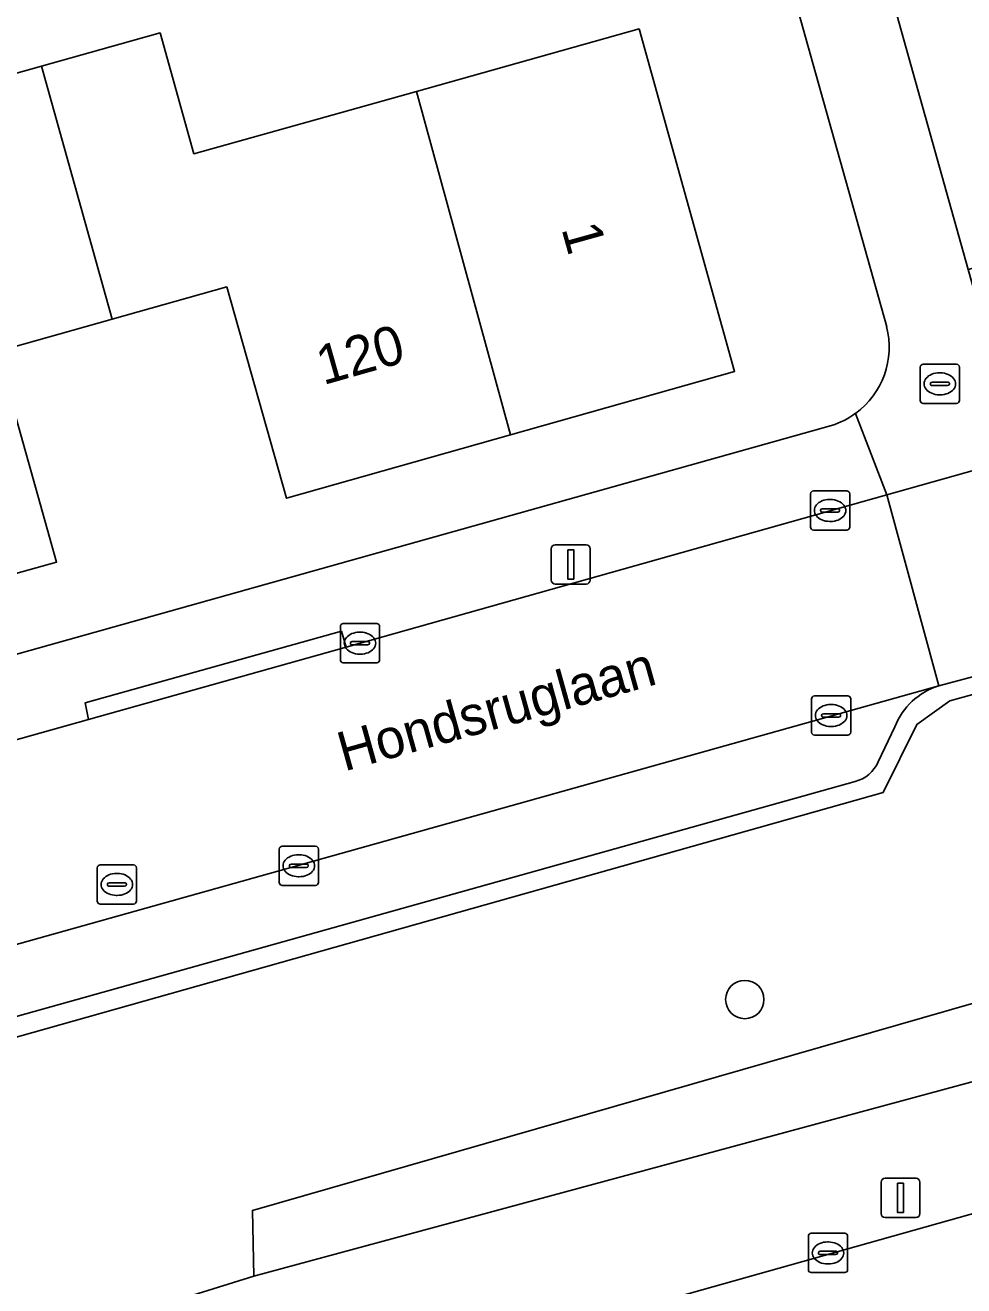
# Model space of a CAD drawing. Extents: x 159626 to 160723, y 388173 to 389416.
# Drawn here: x 160071.4 to 160095.34, y 388295.24 to 388327.38 of the extents above; entities that cross this region are included whole.
import ezdxf

# ---------------------------------------------------------------- set-up
doc = ezdxf.new("R2010")
doc.units = 0
for name, color, linetype in [('IMGEO_Boom', 7, 'Continuous'), ('IMGEO_Brandkraan', 7, 'Continuous'), ('IMGEO_Erf', 7, 'Continuous'), ('IMGEO_Groenvoorziening', 7, 'Continuous'), ('IMGEO_Kolk', 7, 'Continuous'), ('IMGEO_Lichtmast', 7, 'Continuous'), ('IMGEO_Muur', 7, 'Continuous'), ('IMGEO_Openbare_ruimte_label', 7, 'Continuous'), ('IMGEO_Pand', 7, 'Continuous'), ('IMGEO_Pand_nummerreeks', 7, 'Continuous'), ('IMGEO_Parkeervlak_open', 7, 'Continuous'), ('IMGEO_Rijbaan_lokaal_open', 7, 'Continuous'), ('IMGEO_Rijbaan_regionaal_gesloten', 7, 'Continuous'), ('IMGEO_Rioolput', 7, 'Continuous'), ('IMGEO_Voetpad_open', 7, 'Continuous')]:
    doc.layers.add(name, color=color, linetype=linetype)

msp = doc.modelspace()

# ---------------------------------------------------------------- linework, layer by layer
at = {"layer": 'IMGEO_Boom'}
msp.add_circle((160089.755, 388302.536), 0.489, dxfattribs=at)
at = {"layer": 'IMGEO_Brandkraan'}
for p, q in [((160094.304, 388318.738), (160095.156, 388318.738)), ((160094.229, 388317.812), (160094.229, 388318.664)), ((160094.717, 388318.518), (160094.742, 388318.518)), ((160095.23, 388318.664), (160095.23, 388317.812)), ((160094.488, 388318.232), (160094.488, 388318.244)), ((160094.926, 388318.195), (160094.528, 388318.195)), ((160094.531, 388318.281), (160094.929, 388318.281)), ((160094.972, 388318.244), (160094.972, 388318.232)), ((160094.74, 388317.958), (160094.715, 388317.958)), ((160095.156, 388317.738), (160094.304, 388317.738))]:
    msp.add_line(p, q, dxfattribs=at)
for points in [[(160094.304, 388318.738), (160095.156, 388318.738)], [(160094.229, 388317.812), (160094.229, 388318.664)], [(160095.23, 388318.664), (160095.23, 388317.812)], [(160095.156, 388317.738), (160094.304, 388317.738)]]:
    msp.add_lwpolyline(points, dxfattribs=at)
for centre, radius, start, end in [((160094.306, 388318.662), 0.0765, 91.552, 178.448), ((160094.306, 388318.662), 0.0765, 91.552, 178.448), ((160095.154, 388318.662), 0.0765, 1.552, 88.448), ((160095.154, 388318.662), 0.0765, 1.552, 88.448), ((160094.528, 388318.241), 0.0403, 85.8775, 175.7526), ((160094.525, 388318.231), 0.0366, 178.938, 274.7102), ((160094.929, 388318.238), 0.043, 264.8664, 352.4533), ((160094.933, 388318.243), 0.0386, 1.7309, 96.639), ((160094.306, 388317.814), 0.0765, 181.552, 268.448), ((160094.306, 388317.814), 0.0765, 181.552, 268.448), ((160095.154, 388317.814), 0.0765, 271.552, 358.448), ((160095.154, 388317.814), 0.0765, 271.552, 358.448)]:
    msp.add_arc(centre, radius, start, end, dxfattribs=at)
for centre, major_axis, ratio, start_param, end_param in [((160094.716, 388318.238), (-0.387, 0.002), 0.722429, 4.712389, 7.853982), ((160094.741, 388318.238), (-0.39, 0.002), 0.717154, 1.570796, 4.712389)]:
    msp.add_ellipse(centre, major_axis=major_axis, ratio=ratio, start_param=start_param, end_param=end_param, dxfattribs=at)
at = {"layer": 'IMGEO_Erf'}
for points in [[(160093.373, 388319.695), (160091.694, 388325.686), (160087.996, 388338.877), (160074.295, 388387.755)], [(160070.029, 388325.837), (160071.818, 388326.338), (160074.843, 388327.186), (160075.705, 388324.106), (160081.382, 388325.697), (160087.061, 388327.289), (160089.494, 388318.556), (160083.782, 388316.937), (160078.07, 388315.318), (160076.543, 388320.71), (160073.618, 388319.888), (160070.691, 388319.065), (160072.202, 388313.692), (160066.465, 388312.092)], [(160039.23, 388302.377), (160091.966, 388317.174)]]:
    msp.add_lwpolyline(points, dxfattribs=at)
for centre, radius, start, end in [((160091.34, 388319.177), 2.098, 306.2576, 14.31), ((160091.336, 388319.183), 2.105, 287.4032, 306.2475)]:
    msp.add_arc(centre, radius, start, end, dxfattribs=at)
at = {"layer": 'IMGEO_Groenvoorziening'}
for points in [[(160111.162, 388314.606), (160094.986, 388310.154), (160094.139, 388309.551), (160093.281, 388307.812), (160046.081, 388294.496), (160053.63, 388288.927), (160054.524, 388285.955)], [(160114.554, 388302.646), (160113.805, 388305.375), (160077.234, 388295.478), (160060.904, 388290.398), (160060.65, 388290.319), (160055.595, 388289.524), (160056.59, 388286.1), (160101.232, 388298.671)], [(160055.017, 388285.657), (160056.59, 388286.1), (160055.595, 388289.524), (160060.65, 388290.319), (160060.904, 388290.398), (160077.234, 388295.478), (160077.196, 388297.158), (160101.531, 388304.151)]]:
    msp.add_lwpolyline(points, dxfattribs=at)
msp.add_lwpolyline([(160077.234, 388295.478), (160113.805, 388305.375), (160101.531, 388304.151), (160077.196, 388297.158)], close=True, dxfattribs=at)
at = {"layer": 'IMGEO_Kolk'}
for p, q in [((160091.429, 388314.582), (160091.429, 388315.434)), ((160091.504, 388315.508), (160092.356, 388315.508)), ((160091.917, 388315.288), (160091.942, 388315.288)), ((160092.43, 388315.434), (160092.43, 388314.582)), ((160091.688, 388315.002), (160091.688, 388315.014)), ((160092.126, 388314.965), (160091.728, 388314.965)), ((160091.731, 388315.051), (160092.129, 388315.051)), ((160092.172, 388315.014), (160092.172, 388315.002)), ((160091.94, 388314.728), (160091.915, 388314.728)), ((160092.356, 388314.508), (160091.504, 388314.508)), ((160079.441, 388311.198), (160079.441, 388312.05)), ((160079.516, 388312.124), (160080.368, 388312.124)), ((160080.442, 388312.05), (160080.442, 388311.198)), ((160079.743, 388311.667), (160080.141, 388311.667)), ((160079.929, 388311.904), (160079.954, 388311.904)), ((160079.7, 388311.618), (160079.7, 388311.63)), ((160080.138, 388311.581), (160079.74, 388311.581)), ((160079.952, 388311.344), (160079.927, 388311.344)), ((160080.184, 388311.63), (160080.184, 388311.618)), ((160080.368, 388311.124), (160079.516, 388311.124)), ((160091.456, 388309.353), (160091.456, 388310.205)), ((160091.531, 388310.279), (160092.383, 388310.279)), ((160091.944, 388310.059), (160091.969, 388310.059)), ((160092.457, 388310.205), (160092.457, 388309.353)), ((160091.715, 388309.773), (160091.715, 388309.785)), ((160092.153, 388309.736), (160091.755, 388309.736)), ((160091.758, 388309.822), (160092.156, 388309.822)), ((160092.199, 388309.785), (160092.199, 388309.773)), ((160091.967, 388309.499), (160091.942, 388309.499)), ((160092.383, 388309.279), (160091.531, 388309.279)), ((160077.881, 388305.521), (160077.881, 388306.373)), ((160077.956, 388306.447), (160078.808, 388306.447)), ((160078.369, 388306.227), (160078.394, 388306.227)), ((160078.882, 388306.373), (160078.882, 388305.521)), ((160078.14, 388305.941), (160078.14, 388305.953)), ((160078.578, 388305.904), (160078.18, 388305.904)), ((160078.183, 388305.99), (160078.581, 388305.99)), ((160078.624, 388305.953), (160078.624, 388305.941)), ((160078.392, 388305.667), (160078.367, 388305.667)), ((160078.808, 388305.447), (160077.956, 388305.447)), ((160091.451, 388296.573), (160092.303, 388296.573)), ((160091.376, 388295.647), (160091.376, 388296.499)), ((160091.864, 388296.353), (160091.889, 388296.353)), ((160092.377, 388296.499), (160092.377, 388295.647)), ((160091.635, 388296.067), (160091.635, 388296.079)), ((160092.073, 388296.03), (160091.675, 388296.03)), ((160091.678, 388296.116), (160092.076, 388296.116)), ((160092.119, 388296.079), (160092.119, 388296.067)), ((160091.887, 388295.793), (160091.862, 388295.793)), ((160092.303, 388295.573), (160091.451, 388295.573))]:
    msp.add_line(p, q, dxfattribs=at)
for points in [[(160091.429, 388314.582), (160091.429, 388315.434)], [(160091.504, 388315.508), (160092.356, 388315.508)], [(160092.43, 388315.434), (160092.43, 388314.582)], [(160092.356, 388314.508), (160091.504, 388314.508)], [(160079.441, 388311.198), (160079.441, 388312.05)], [(160079.516, 388312.124), (160080.368, 388312.124)], [(160080.442, 388312.05), (160080.442, 388311.198)], [(160080.368, 388311.124), (160079.516, 388311.124)], [(160091.456, 388309.353), (160091.456, 388310.205)], [(160091.531, 388310.279), (160092.383, 388310.279)], [(160092.457, 388310.205), (160092.457, 388309.353)], [(160092.383, 388309.279), (160091.531, 388309.279)], [(160077.881, 388305.521), (160077.881, 388306.373)], [(160077.956, 388306.447), (160078.808, 388306.447)], [(160078.882, 388306.373), (160078.882, 388305.521)], [(160078.808, 388305.447), (160077.956, 388305.447)], [(160091.451, 388296.573), (160092.303, 388296.573)], [(160091.376, 388295.647), (160091.376, 388296.499)], [(160092.377, 388296.499), (160092.377, 388295.647)], [(160092.303, 388295.573), (160091.451, 388295.573)]]:
    msp.add_lwpolyline(points, dxfattribs=at)
for centre, radius, start, end in [((160091.506, 388315.432), 0.0765, 91.552, 178.448), ((160091.506, 388315.432), 0.0765, 91.552, 178.448), ((160092.354, 388315.432), 0.0765, 1.552, 88.448), ((160092.354, 388315.432), 0.0765, 1.552, 88.448), ((160091.728, 388315.011), 0.0403, 85.8775, 175.7526), ((160091.725, 388315.001), 0.0366, 178.938, 274.7102), ((160092.129, 388315.008), 0.043, 264.8664, 352.4533), ((160092.133, 388315.013), 0.0386, 1.7309, 96.639), ((160091.506, 388314.584), 0.0765, 181.552, 268.448), ((160091.506, 388314.584), 0.0765, 181.552, 268.448), ((160092.354, 388314.584), 0.0765, 271.552, 358.448), ((160092.354, 388314.584), 0.0765, 271.552, 358.448), ((160079.518, 388312.048), 0.0765, 91.552, 178.448), ((160079.518, 388312.048), 0.0765, 91.552, 178.448), ((160080.366, 388312.048), 0.0765, 1.552, 88.448), ((160080.366, 388312.048), 0.0765, 1.552, 88.448), ((160079.74, 388311.627), 0.0403, 85.8775, 175.7526), ((160080.145, 388311.629), 0.0386, 1.7309, 96.639), ((160079.737, 388311.617), 0.0366, 178.938, 274.7102), ((160080.141, 388311.624), 0.043, 264.8664, 352.4533), ((160079.518, 388311.2), 0.0765, 181.552, 268.448), ((160079.518, 388311.2), 0.0765, 181.552, 268.448), ((160080.366, 388311.2), 0.0765, 271.552, 358.448), ((160080.366, 388311.2), 0.0765, 271.552, 358.448), ((160091.533, 388310.203), 0.0765, 91.552, 178.448), ((160091.533, 388310.203), 0.0765, 91.552, 178.448), ((160092.381, 388310.203), 0.0765, 1.552, 88.448), ((160092.381, 388310.203), 0.0765, 1.552, 88.448), ((160091.755, 388309.782), 0.0403, 85.8775, 175.7526), ((160091.752, 388309.772), 0.0366, 178.938, 274.7102), ((160092.156, 388309.779), 0.043, 264.8664, 352.4533), ((160092.16, 388309.784), 0.0386, 1.7309, 96.639), ((160091.533, 388309.355), 0.0765, 181.552, 268.448), ((160091.533, 388309.355), 0.0765, 181.552, 268.448), ((160092.381, 388309.355), 0.0765, 271.552, 358.448), ((160092.381, 388309.355), 0.0765, 271.552, 358.448), ((160077.958, 388306.371), 0.0765, 91.552, 178.448), ((160077.958, 388306.371), 0.0765, 91.552, 178.448), ((160078.806, 388306.371), 0.0765, 1.552, 88.448), ((160078.806, 388306.371), 0.0765, 1.552, 88.448), ((160078.18, 388305.95), 0.0403, 85.8775, 175.7526), ((160078.177, 388305.94), 0.0366, 178.938, 274.7102), ((160078.581, 388305.947), 0.043, 264.8664, 352.4533), ((160078.585, 388305.952), 0.0386, 1.7309, 96.639), ((160077.958, 388305.523), 0.0765, 181.552, 268.448), ((160077.958, 388305.523), 0.0765, 181.552, 268.448), ((160078.806, 388305.523), 0.0765, 271.552, 358.448), ((160078.806, 388305.523), 0.0765, 271.552, 358.448), ((160091.453, 388296.497), 0.0765, 91.552, 178.448), ((160091.453, 388296.497), 0.0765, 91.552, 178.448), ((160092.301, 388296.497), 0.0765, 1.552, 88.448), ((160092.301, 388296.497), 0.0765, 1.552, 88.448), ((160091.675, 388296.076), 0.0403, 85.8775, 175.7526), ((160091.672, 388296.066), 0.0366, 178.938, 274.7102), ((160092.076, 388296.073), 0.043, 264.8664, 352.4533), ((160092.08, 388296.078), 0.0386, 1.7309, 96.639), ((160091.453, 388295.649), 0.0765, 181.552, 268.448), ((160091.453, 388295.649), 0.0765, 181.552, 268.448), ((160092.301, 388295.649), 0.0765, 271.552, 358.448), ((160092.301, 388295.649), 0.0765, 271.552, 358.448)]:
    msp.add_arc(centre, radius, start, end, dxfattribs=at)
for centre, major_axis, ratio, start_param, end_param in [((160091.916, 388315.008), (-0.387, 0.002), 0.722429, 4.712389, 7.853982), ((160091.941, 388315.008), (-0.39, 0.002), 0.717154, 1.570796, 4.712389), ((160079.928, 388311.624), (-0.387, 0.002), 0.722429, 4.712389, 7.853982), ((160079.953, 388311.624), (-0.39, 0.002), 0.717154, 1.570796, 4.712389), ((160091.943, 388309.779), (-0.387, 0.002), 0.722429, 4.712389, 7.853982), ((160091.968, 388309.779), (-0.39, 0.002), 0.717154, 1.570796, 4.712389), ((160078.368, 388305.947), (-0.387, 0.002), 0.722429, 4.712389, 7.853982), ((160078.393, 388305.947), (-0.39, 0.002), 0.717154, 1.570796, 4.712389), ((160091.863, 388296.073), (-0.387, 0.002), 0.722429, 4.712389, 7.853982), ((160091.888, 388296.073), (-0.39, 0.002), 0.717154, 1.570796, 4.712389)]:
    msp.add_ellipse(centre, major_axis=major_axis, ratio=ratio, start_param=start_param, end_param=end_param, dxfattribs=at)
at = {"layer": 'IMGEO_Lichtmast'}
for p, q in [((160084.821, 388313.232), (160084.821, 388314.032)), ((160084.821, 388314.032), (160084.821, 388313.232)), ((160084.921, 388314.132), (160085.711, 388314.132)), ((160085.711, 388314.132), (160084.921, 388314.132)), ((160085.811, 388314.032), (160085.811, 388313.232)), ((160085.811, 388313.232), (160085.811, 388314.032)), ((160085.711, 388313.132), (160084.921, 388313.132)), ((160084.921, 388313.132), (160085.711, 388313.132)), ((160093.232, 388297.077), (160093.232, 388297.877)), ((160093.232, 388297.877), (160093.232, 388297.077)), ((160093.332, 388297.977), (160094.122, 388297.977)), ((160094.122, 388297.977), (160093.332, 388297.977)), ((160094.222, 388297.877), (160094.222, 388297.077)), ((160094.222, 388297.077), (160094.222, 388297.877)), ((160094.122, 388296.977), (160093.332, 388296.977)), ((160093.332, 388296.977), (160094.122, 388296.977))]:
    msp.add_line(p, q, dxfattribs=at)
for points in [[(160085.241, 388314.007), (160085.391, 388314.007), (160085.391, 388313.257), (160085.241, 388313.257), (160085.241, 388314.007)], [(160093.652, 388297.852), (160093.802, 388297.852), (160093.802, 388297.102), (160093.652, 388297.102), (160093.652, 388297.852)]]:
    msp.add_lwpolyline(points, dxfattribs=at)
for centre, start, end in [((160084.921, 388314.032), 90, 180), ((160084.921, 388314.032), 90, 180), ((160085.711, 388314.032), 0, 90), ((160085.711, 388314.032), 360, 90), ((160084.921, 388313.232), 180, 270), ((160084.921, 388313.232), 180, 270), ((160085.711, 388313.232), 270, 0), ((160085.711, 388313.232), 270, 0), ((160093.332, 388297.877), 90, 180), ((160093.332, 388297.877), 90, 180), ((160094.122, 388297.877), 0, 90), ((160094.122, 388297.877), 360, 90), ((160093.332, 388297.077), 180, 270), ((160093.332, 388297.077), 180, 270), ((160094.122, 388297.077), 270, 0), ((160094.122, 388297.077), 270, 0)]:
    msp.add_arc(centre, 0.1, start, end, dxfattribs=at)
at = {"layer": 'IMGEO_Muur'}
msp.add_lwpolyline([(160091.694, 388325.686), (160087.996, 388338.877)], dxfattribs=at)
at = {"layer": 'IMGEO_Pand'}
for points in [[(160073.618, 388319.888), (160076.543, 388320.71), (160078.07, 388315.318), (160083.782, 388316.937), (160081.382, 388325.697), (160075.705, 388324.106), (160074.843, 388327.186), (160071.818, 388326.338)], [(160081.382, 388325.697), (160083.782, 388316.937), (160089.494, 388318.556), (160087.061, 388327.289)], [(160073.618, 388319.888), (160071.818, 388326.338), (160070.029, 388325.837), (160068.79, 388325.49), (160069.653, 388322.411), (160064.024, 388320.833), (160066.465, 388312.092), (160072.202, 388313.692), (160070.691, 388319.065)]]:
    msp.add_lwpolyline(points, close=True, dxfattribs=at)
at = {"layer": 'IMGEO_Parkeervlak_open'}
for points in [[(160094.7, 388310.535), (160046.003, 388296.881)], [(160093.155, 388308.597), (160093.582, 388309.494)], [(160049.138, 388295.93), (160092.571, 388308.096)]]:
    msp.add_lwpolyline(points, dxfattribs=at)
for centre, radius, start, end in [((160095.221, 388308.854), 1.76, 107.233, 158.6819), ((160092.359, 388308.934), 0.864, 284.1778, 337.0733)]:
    msp.add_arc(centre, radius, start, end, dxfattribs=at)
at = {"layer": 'IMGEO_Rijbaan_lokaal_open'}
for points in [[(160095.449, 388321.154), (160100.358, 388322.544), (160083.883, 388381.26), (160084.141, 388382.584), (160085.382, 388385.449), (160140.604, 388400.943), (160147.918, 388403.002), (160146.522, 388407.997), (160139.18, 388405.917), (160076.62, 388388.378)], [(160104.347, 388318.485), (160101.723, 388317.748), (160096.819, 388316.372), (160093.373, 388315.405), (160094.7, 388310.535), (160105.751, 388313.488), (160105.719, 388313.602)], [(160079.586, 388311.525), (160073.017, 388309.68), (160062.717, 388306.786), (160056.177, 388304.949), (160042.215, 388301.025), (160043.548, 388296.168), (160046.003, 388296.881), (160094.7, 388310.535), (160093.373, 388315.405)]]:
    msp.add_lwpolyline(points, close=True, dxfattribs=at)
at = {"layer": 'IMGEO_Rijbaan_regionaal_gesloten'}
msp.add_lwpolyline([(160101.232, 388298.671), (160056.59, 388286.1), (160055.017, 388285.657), (160056.119, 388282.353), (160100.533, 388294.851)], dxfattribs=at)
at = {"layer": 'IMGEO_Rioolput'}
for p, q in [((160073.241, 388305.045), (160073.241, 388305.897)), ((160073.316, 388305.971), (160074.168, 388305.971)), ((160074.242, 388305.897), (160074.242, 388305.045)), ((160073.729, 388305.751), (160073.754, 388305.751)), ((160073.5, 388305.465), (160073.5, 388305.477)), ((160073.938, 388305.428), (160073.54, 388305.428)), ((160073.543, 388305.514), (160073.941, 388305.514)), ((160073.984, 388305.477), (160073.984, 388305.465)), ((160074.168, 388304.971), (160073.316, 388304.971)), ((160073.752, 388305.191), (160073.727, 388305.191))]:
    msp.add_line(p, q, dxfattribs=at)
for points in [[(160073.241, 388305.045), (160073.241, 388305.897)], [(160073.316, 388305.971), (160074.168, 388305.971)], [(160074.242, 388305.897), (160074.242, 388305.045)], [(160074.168, 388304.971), (160073.316, 388304.971)]]:
    msp.add_lwpolyline(points, dxfattribs=at)
for centre, radius, start, end in [((160073.318, 388305.895), 0.0765, 91.552, 178.448), ((160073.318, 388305.895), 0.0765, 91.552, 178.448), ((160074.166, 388305.895), 0.0765, 1.552, 88.448), ((160074.166, 388305.895), 0.0765, 1.552, 88.448), ((160073.54, 388305.474), 0.0403, 85.8775, 175.7526), ((160073.537, 388305.464), 0.0366, 178.938, 274.7102), ((160073.941, 388305.471), 0.043, 264.8664, 352.4533), ((160073.945, 388305.476), 0.0386, 1.7309, 96.639), ((160073.318, 388305.047), 0.0765, 181.552, 268.448), ((160073.318, 388305.047), 0.0765, 181.552, 268.448), ((160074.166, 388305.047), 0.0765, 271.552, 358.448), ((160074.166, 388305.047), 0.0765, 271.552, 358.448)]:
    msp.add_arc(centre, radius, start, end, dxfattribs=at)
for centre, major_axis, ratio, start_param, end_param in [((160073.728, 388305.471), (-0.387, 0.002), 0.722429, 4.712389, 7.853982), ((160073.753, 388305.471), (-0.39, 0.002), 0.717154, 1.570796, 4.712389)]:
    msp.add_ellipse(centre, major_axis=major_axis, ratio=ratio, start_param=start_param, end_param=end_param, dxfattribs=at)
at = {"layer": 'IMGEO_Voetpad_open'}
for points in [[(160066.558, 388421.402), (160067.42, 388418.389), (160065.847, 388417.956), (160066.106, 388417.028), (160066.272, 388416.435), (160067.606, 388411.669), (160069.255, 388405.772), (160069.651, 388404.355), (160070.165, 388402.519), (160074.295, 388387.755), (160087.996, 388338.877), (160091.694, 388325.686), (160093.373, 388319.695)], [(160092.581, 388317.485), (160093.373, 388315.405), (160096.819, 388316.372), (160096.225, 388318.411), (160095.449, 388321.154), (160076.62, 388388.378), (160139.18, 388405.917), (160146.522, 388407.997), (160145.513, 388411.698)], [(160093.373, 388315.405), (160092.581, 388317.485)], [(160091.966, 388317.174), (160039.23, 388302.377), (160042.215, 388301.025), (160056.177, 388304.949), (160056.068, 388305.379), (160062.609, 388307.206), (160062.717, 388306.786), (160073.017, 388309.68), (160072.935, 388310.1), (160079.473, 388311.926), (160079.586, 388311.525), (160093.373, 388315.405)], [(160093.281, 388307.812), (160094.139, 388309.551), (160094.986, 388310.154), (160111.162, 388314.606)], [(160110.801, 388314.798), (160110.618, 388314.778), (160105.751, 388313.488), (160094.7, 388310.535)], [(160093.582, 388309.494), (160093.155, 388308.597)], [(160046.003, 388296.881), (160043.548, 388296.168), (160046.081, 388294.496), (160093.281, 388307.812)], [(160092.571, 388308.096), (160049.138, 388295.93)]]:
    msp.add_lwpolyline(points, dxfattribs=at)
msp.add_lwpolyline([(160079.586, 388311.525), (160079.473, 388311.926), (160072.935, 388310.1), (160073.017, 388309.68)], close=True, dxfattribs=at)
for centre, radius, start, end in [((160091.34, 388319.177), 2.098, 306.2576, 14.31), ((160091.336, 388319.183), 2.105, 287.4032, 306.2475), ((160095.221, 388308.854), 1.76, 107.233, 158.6819), ((160092.359, 388308.934), 0.864, 284.1778, 337.0733)]:
    msp.add_arc(centre, radius, start, end, dxfattribs=at)

# ---------------------------------------------------------------- texts
at = {"layer": 'IMGEO_Openbare_ruimte_label'}
msp.add_text('Hondsruglaan', height=1, rotation=15.6069, dxfattribs=at).set_placement((160079.54, 388308.349))
at = {"layer": 'IMGEO_Pand_nummerreeks'}
for s, rotation, p in [('1', 285.5678, (160085.075, 388322.197)), ('120', 15.8248, (160079.004, 388318.202))]:
    msp.add_text(s, height=1, rotation=rotation, dxfattribs=at).set_placement(p)

doc.saveas('drawing.dxf')
